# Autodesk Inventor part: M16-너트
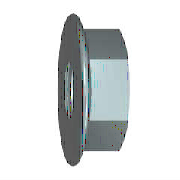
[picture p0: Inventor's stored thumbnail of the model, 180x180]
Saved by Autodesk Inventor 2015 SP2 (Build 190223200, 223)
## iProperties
IsCustomPart: 0
Company: 한국ATC센터
Created: 2009-02
Part Number: M16-너트
Material: Steel, Mild
Description: 플랜지붙이 6각 너트
Document SubType Name: Modeling
Standard: JIS B 1190
Designer: KYOUNG IL JANG
Standards Organization: JIS
Language: ko-KR
Size Designation: M 16
Categories: <MemberInstance><Categories><Category DisplayName="조임쇠" InternalName="e4da775c-781d-43d5-af7c-5136215cf5a6" Mnemonic="FSTN"><Category DisplayName="너트" InternalN
Density: 1 g/cm^3
Appearance: Metal-Steel
Author: KYOUNG IL JANG
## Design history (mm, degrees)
sketch "스케치1"
  geometry: L1 (-3.414, 0)-(18.069, 0) reference; L2 (6.015, 11)-(3.359, 15.6); L3 (6.015, 11)-(15, 11); L4 (15, 11)-(15, 0); L5 (6.015, 11)-(6.015, 0); L6 (0, -3.378)-(0, 20.266) reference; A1 r 1.8 centre (1.8, 14.7) between (3.359, 15.6) and (0, 14.7); 1 further point
  constraints: 8 end point, 3 point on line, 2 perpendicular, 2 point on circle, 2 tangent, 1 centre point, 1 parallel
  dimensions: "d2" = 22 diameter of L3 L1 (= SW); "d4" = 33 dimension on A1 L1 (= LADI); "d5" = 1.8 radius of A1 (= PHH); "d15" = 15 distance between parallel lines of L4 L6 (= KOH); "d16" = 30 deg angle of L6 L2 (= KEWI)
revolve "링" sketch "스케치1" stored, may be unused: angle "d8" = 90 deg
sketch "스케치2"
  geometry: L1 (-11, -6.351)-(-11, 6.351); L2 (-11, 6.351)-(0, 12.702); L3 (0, 12.702)-(11, 6.351); L4 (11, 6.351)-(11, -6.351); L5 (11, -6.351)-(0, -12.702); L6 (0, -12.702)-(-11, -6.351); C1 r 4.9 at (0, 0); C2 r 14.7 at (0, 0) reference; 1 further point
  constraints: 12 end point, 1 centre point, 1 coincident, 1 vertical, 11 other
  dimensions: "d6" = 25.40341 distance of L5.end L2.end (= 1.1547 x SW)
extrude "본체" join sketch "스케치2" distance "d7" = 15 (= KOH); taper "d9" = 0 deg
sketch "스케치3"
  geometry: L1 (5.032, 12.702)-(15, 12.702) reference; L2 (15, 6.351)-(15, 12.702) reference; L3 (0, -14.7)-(0, 14.7) reference; L4 (-3, 0)-(18, 0) reference; L5 (14.018, 12.702)-(15, 11)
  constraints: 2 end point, 2 point on line
  dimensions: "d10" = 30 deg angle of L2 L5 (= ANG1); "d11" = 22 diameter of L5.end L4 (= SW0)
revolve "모따기1" sketch "스케치3" stored, may be unused: angle "d24" = 90 deg
sketch "스케치4"
  geometry: C1 r 14.7 at (0, 0) reference; 1 further point
  constraints: 1 coincident
hole "스레드" sketch "스케치4" at (0, 0) diameter "d25" = 13.835; stored, may be unused: countersink angle "d29" = 82 deg, drill point angle "d31" = 118 deg; dims "d26" = 6, "d27" = 4, "d28" = 2, "d30" = 8
workaxis "Work Axis1"
workplane "Work Plane1"
body "Solid1"
chamfer "모따기2" distance "d12" = 1.08253 (= -0.5 x GD1 + 0.5 x NND); stored, may be unused: angle "d13" = 30 deg, second distance "d46" = 1.08253 (= -0.5 x GD1 + 0.5 x NND)
chamfer "모따기3" distance "d51" = 1.08253 (= -0.5 x GD1 + 0.5 x NND); stored, may be unused: second distance "d52" = 2, angle "d53" = 45 deg
other parameters: "ANG1" = 30 deg [user parameter; used in 1 equation term], "KEWI" = 30 deg [user parameter; used in 1 equation term], "NND" = 16 [user parameter; used in 3 equation terms], "LADI" = 33 [user parameter; used in 2 equation terms], "SW" = 22 [user parameter; used in 4 equation terms], "PHH" = 1.8 [user parameter; used in 2 equation terms], "KOH" = 15 [user parameter; used in 2 equation terms], "SW0" = 22 (= SW) [user parameter; used in 1 equation term], "GD1" = 13.83494 (computed from THREADDIA, PTC, TOA) [user parameter; used in 3 equation terms], "d1" = 33 (= LADI), "d3" = 1.8 (= PHH), "d45" = 0, "d47" = 0, "d49" = 0, "d54" = 0, "GUL" = 1.08253 (= 0.541266 x PTC) [user parameter], "TPU" = 5 (computed from PTC) [user parameter], "RR" = 2 [user parameter], "THREADDIA" = 16 [user parameter; used in 1 equation term], "TOA" = 30 deg [user parameter; used in 1 equation term], "PTC" = 2 [user parameter; used in 4 equation terms], "GAL" = 1.08253 (= 0.541266 x PTC) [user parameter], "E0" = 25.41 (= 1.155 x SW) [user parameter]
